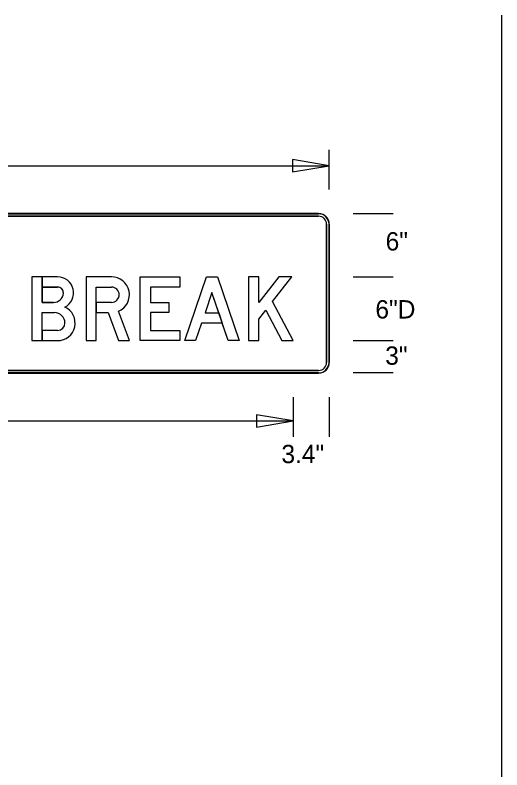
# Model space of a CAD drawing. Extents: x 0 to 770, y 0 to 495.
# Drawn here: x 292 to 385, y 350.9 to 495 of the extents above; entities that cross this region are included whole.
import ezdxf

# ---------------------------------------------------------------- set-up
doc = ezdxf.new("R2010")
doc.units = 0
for name, color, linetype in [('Dimension', 7, 'Continuous'), ('GSBWFill', 7, 'Continuous'), ('GSColorFill', 7, 'Continuous'), ('GSDims', 7, 'Continuous'), ('GSOutline', 7, 'Continuous'), ('SheetLines_dp', 7, 'Continuous'), ('TextStructures', 7, 'Continuous')]:
    doc.layers.add(name, color=color, linetype=linetype)

msp = doc.modelspace()

# ---------------------------------------------------------------- linework, layer by layer
at = {"layer": 'Dimension'}
for points in [[(352.02, 466.25), (345, 467.44), (345, 465.06)], [(345.14, 417.53), (338.12, 418.72), (338.12, 416.34)]]:
    msp.add_lwpolyline(points, close=True, dxfattribs=at)
at = {"layer": 'GSBWFill'}
for p, q in [((349.99, 457.12), (220.05, 457.12)), ((349.99, 457.12), (220.05, 457.12)), ((220.05, 456.61), (349.99, 456.61)), ((351.51, 455.09), (351.51, 428.69)), ((352.02, 428.69), (352.02, 455.09)), ((352.02, 428.69), (352.02, 455.09)), ((307.49, 443.09), (310.42, 443.09)), ((297.14, 438.22), (299.52, 438.22)), ((220.05, 426.66), (349.99, 426.66)), ((349.99, 427.17), (220.06, 427.17)), ((220.06, 426.66), (349.99, 426.66))]:
    msp.add_line(p, q, dxfattribs=at)
for points in [[(299.34, 440.16), (297.14, 440.16), (297.14, 445.04), (295.19, 445.04), (295.19, 432.86), (297.14, 432.86), (297.14, 438.22)], [(300.12, 445.04), (297.14, 445.04), (297.14, 443.09), (300.12, 443.09)], [(310.42, 445.04), (305.55, 445.04), (305.55, 432.86), (307.49, 432.86), (307.49, 443.09)], [(310.42, 440.16), (307.5, 440.16), (307.5, 438.22), (309.78, 438.22), (311.75, 432.86), (313.83, 432.86), (311.76, 438.49)], [(300.12, 434.8), (297.14, 434.8), (297.14, 432.86), (300.12, 432.86)]]:
    msp.add_lwpolyline(points, dxfattribs=at)
for points in [[(323.45, 443.09), (317.85, 443.09), (317.85, 440.16), (321.39, 440.16), (321.39, 438.22), (317.85, 438.22), (317.85, 434.8), (323.45, 434.8), (323.45, 432.86), (315.9, 432.86), (315.9, 445.04), (323.45, 445.04)], [(324.43, 432.86), (328.57, 445.04), (330.64, 445.04), (334.78, 432.86), (332.72, 432.86), (329.6, 442.03), (328.29, 438.15), (330.92, 438.15), (331.58, 436.2), (327.62, 436.2), (326.49, 432.86)], [(338.56, 432.86), (338.56, 436.98), (339.88, 438.66), (342.93, 432.86), (345.14, 432.86), (341.19, 440.34), (344.88, 445.04), (342.41, 445.04), (338.56, 440.14), (338.56, 445.04), (336.61, 445.04), (336.61, 432.86)]]:
    msp.add_lwpolyline(points, close=True, dxfattribs=at)
for centre, radius, start, end in [((349.99, 455.09), 2.03, 0, 90), ((349.99, 455.09), 2.03, 0, 90), ((349.99, 455.09), 1.52, 0, 90), ((300.12, 441.99), 3.05, 296.5254, 90), ((310.42, 441.63), 3.41, 293.1324, 90), ((300.12, 441.99), 1.1, 355.5883, 90), ((310.42, 441.63), 1.46, 270, 90), ((299.34, 442.05), 1.89, 270, 355.5883), ((299.52, 436.21), 2.01, 0, 90), ((300.12, 436.21), 3.35, 270, 66.0465), ((300.12, 436.21), 1.4, 270, 0), ((349.99, 428.69), 2.03, 270, 0), ((349.99, 428.69), 1.52, 270, 0), ((349.99, 428.69), 2.03, 270, 0)]:
    msp.add_arc(centre, radius, start, end, dxfattribs=at)
at = {"layer": 'GSColorFill'}
for p, q in [((349.99, 457.12), (220.05, 457.12)), ((349.99, 457.12), (220.05, 457.12)), ((349.99, 457.12), (220.05, 457.12)), ((220.05, 457.07), (349.99, 457.07)), ((220.05, 456.61), (349.99, 456.61)), ((351.51, 455.09), (351.51, 428.69)), ((351.97, 455.09), (351.97, 428.69)), ((352.02, 428.69), (352.02, 455.09)), ((352.02, 428.69), (352.02, 455.09)), ((352.02, 428.69), (352.02, 455.09)), ((307.49, 443.09), (310.42, 443.09)), ((297.14, 438.22), (299.52, 438.22)), ((349.99, 426.71), (220.05, 426.71)), ((220.05, 426.66), (349.99, 426.66)), ((220.05, 426.66), (349.99, 426.66)), ((349.99, 427.17), (220.06, 427.17)), ((220.06, 426.66), (349.99, 426.66))]:
    msp.add_line(p, q, dxfattribs=at)
for points in [[(299.34, 440.16), (297.14, 440.16), (297.14, 445.04), (295.19, 445.04), (295.19, 432.86), (297.14, 432.86), (297.14, 438.22)], [(300.12, 445.04), (297.14, 445.04), (297.14, 443.09), (300.12, 443.09)], [(310.42, 445.04), (305.55, 445.04), (305.55, 432.86), (307.49, 432.86), (307.49, 443.09)], [(310.42, 440.16), (307.5, 440.16), (307.5, 438.22), (309.78, 438.22), (311.75, 432.86), (313.83, 432.86), (311.76, 438.49)], [(300.12, 434.8), (297.14, 434.8), (297.14, 432.86), (300.12, 432.86)]]:
    msp.add_lwpolyline(points, dxfattribs=at)
for points in [[(323.45, 443.09), (317.85, 443.09), (317.85, 440.16), (321.39, 440.16), (321.39, 438.22), (317.85, 438.22), (317.85, 434.8), (323.45, 434.8), (323.45, 432.86), (315.9, 432.86), (315.9, 445.04), (323.45, 445.04)], [(324.43, 432.86), (328.57, 445.04), (330.64, 445.04), (334.78, 432.86), (332.72, 432.86), (329.6, 442.03), (328.29, 438.15), (330.92, 438.15), (331.58, 436.2), (327.62, 436.2), (326.49, 432.86)], [(338.56, 432.86), (338.56, 436.98), (339.88, 438.66), (342.93, 432.86), (345.14, 432.86), (341.19, 440.34), (344.88, 445.04), (342.41, 445.04), (338.56, 440.14), (338.56, 445.04), (336.61, 445.04), (336.61, 432.86)]]:
    msp.add_lwpolyline(points, close=True, dxfattribs=at)
for centre, radius, start, end in [((349.99, 455.09), 2.03, 0, 90), ((349.99, 455.09), 2.03, 0, 90), ((349.99, 455.09), 2.03, 0, 90), ((349.99, 455.09), 1.98, 0, 90), ((349.99, 455.09), 1.52, 0, 90), ((300.12, 441.99), 3.05, 296.5254, 90), ((310.42, 441.63), 3.41, 293.1324, 90), ((300.12, 441.99), 1.1, 355.5883, 90), ((310.42, 441.63), 1.46, 270, 90), ((299.34, 442.05), 1.89, 270, 355.5883), ((299.52, 436.21), 2.01, 0, 90), ((300.12, 436.21), 3.35, 270, 66.0465), ((300.12, 436.21), 1.4, 270, 0), ((349.99, 428.69), 2.03, 270, 0), ((349.99, 428.69), 2.03, 270, 0), ((349.99, 428.69), 1.52, 270, 0), ((349.99, 428.69), 2.03, 270, 0), ((349.99, 428.69), 1.98, 270, 0)]:
    msp.add_arc(centre, radius, start, end, dxfattribs=at)
at = {"layer": 'GSDims'}
for p, q in [((352.02, 461.69), (352.02, 469.3)), ((218.02, 466.25), (352.02, 466.25)), ((356.59, 457.12), (364.2, 457.12)), ((356.59, 445.04), (364.2, 445.04)), ((356.59, 445.04), (364.2, 445.04)), ((356.59, 432.86), (364.2, 432.86)), ((356.59, 432.86), (364.2, 432.86)), ((356.59, 426.77), (364.2, 426.77)), ((345.14, 422.1), (345.14, 414.48)), ((345.14, 422.1), (345.14, 414.48)), ((352.02, 422.1), (352.02, 414.48)), ((224.9, 417.53), (345.14, 417.53))]:
    msp.add_line(p, q, dxfattribs=at)
at = {"layer": 'GSOutline'}
for p, q in [((349.99, 457.12), (220.05, 457.12)), ((349.99, 457.12), (220.05, 457.12)), ((349.99, 456.61), (220.05, 456.61)), ((351.51, 428.69), (351.51, 455.09)), ((352.02, 428.69), (352.02, 455.09)), ((352.02, 428.69), (352.02, 455.09)), ((300.12, 443.09), (297.14, 443.09)), ((297.14, 438.22), (299.52, 438.22)), ((313.83, 432.86), (311.76, 438.49)), ((295.19, 432.86), (300.12, 432.86)), ((220.05, 427.17), (349.99, 427.17)), ((220.05, 426.66), (349.99, 426.66)), ((220.05, 426.66), (349.99, 426.66))]:
    msp.add_line(p, q, dxfattribs=at)
for points in [[(300.12, 445.04), (295.19, 445.04), (295.19, 432.86)], [(310.42, 445.04), (305.55, 445.04), (305.55, 432.86), (307.49, 432.86), (307.49, 438.22), (309.78, 438.22), (311.75, 432.86), (313.83, 432.86)], [(297.14, 443.09), (297.14, 440.16), (299.34, 440.16)], [(310.42, 440.16), (307.49, 440.16), (307.49, 443.09), (310.42, 443.09)], [(300.12, 434.8), (297.14, 434.8), (297.14, 438.22)]]:
    msp.add_lwpolyline(points, dxfattribs=at)
for points in [[(323.45, 443.09), (317.85, 443.09), (317.85, 440.16), (321.39, 440.16), (321.39, 438.22), (317.85, 438.22), (317.85, 434.8), (323.45, 434.8), (323.45, 432.86), (315.9, 432.86), (315.9, 445.04), (323.45, 445.04)], [(327.62, 436.2), (326.49, 432.86), (324.43, 432.86), (328.57, 445.04), (330.64, 445.04), (334.78, 432.86), (332.72, 432.86), (331.58, 436.2)], [(338.56, 432.86), (338.56, 436.98), (339.88, 438.66), (342.93, 432.86), (345.14, 432.86), (341.19, 440.34), (344.88, 445.04), (342.41, 445.04), (338.56, 440.14), (338.56, 445.04), (336.61, 445.04), (336.61, 432.86)], [(328.29, 438.15), (330.92, 438.15), (329.6, 442.03)]]:
    msp.add_lwpolyline(points, close=True, dxfattribs=at)
for centre, radius, start, end in [((349.99, 455.09), 2.03, 0, 90), ((349.99, 455.09), 2.03, 0, 90), ((349.99, 455.09), 1.52, 0, 90), ((300.12, 441.99), 3.05, 296.5254, 90), ((310.42, 441.63), 3.41, 293.1324, 90), ((300.12, 441.99), 1.1, 355.5883, 90), ((310.42, 441.63), 1.46, 270, 90), ((299.34, 442.05), 1.89, 270, 355.5883), ((299.52, 436.21), 2.01, 0, 90), ((300.12, 436.21), 3.35, 270, 66.0465), ((300.12, 436.21), 1.4, 270, 0), ((349.99, 428.69), 2.03, 270, 0), ((349.99, 428.69), 1.52, 270, 0), ((349.99, 428.69), 2.03, 270, 0)]:
    msp.add_arc(centre, radius, start, end, dxfattribs=at)
at = {"layer": 'SheetLines_dp'}
msp.add_line((385, 0), (385, 495), dxfattribs=at)

# ---------------------------------------------------------------- texts
at = {"layer": 'TextStructures'}
for s, p in [('6"', (362.79, 450.07)), ('6"D', (360.83, 437.09)), ('3"', (362.71, 428.26)), ('3.4"', (342.88, 409.48))]:
    msp.add_text(s, height=3.5, dxfattribs=at).set_placement(p)

doc.saveas('drawing.dxf')
